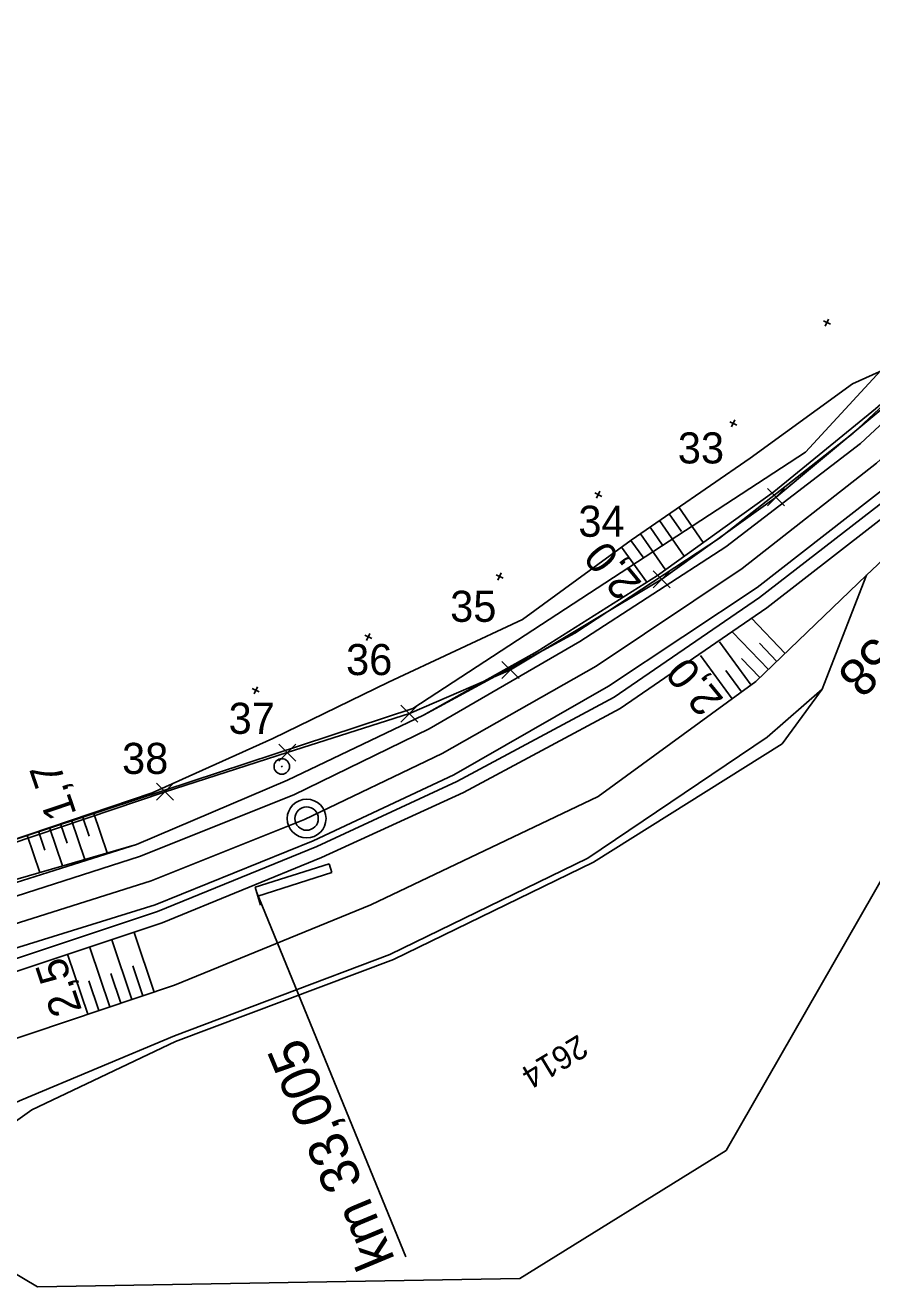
# Model space of a CAD drawing. Extents: x -804166 to -803706, y -1151030 to -1150147.
# Drawn here: x -803964.8 to -803910.3, y -1150743 to -1150661.8 of the extents above; entities that cross this region are included whole.
import ezdxf

# ---------------------------------------------------------------- set-up
doc = ezdxf.new("R2010")
doc.units = 0
for name, color, linetype in [('0381KM032-037P - Vrstva 1', 7, 'Continuous'), ('0381KM032-037P - Vrstva 13', 7, 'Continuous'), ('0381KM032-037P - Vrstva 4', 7, 'Continuous'), ('0381KM032-037P - Vrstva 48', 7, 'Continuous'), ('0381KM032-037P - Vrstva 49', 7, 'Continuous'), ('0381KM032-037P - Vrstva 57', 7, 'Continuous'), ('0381KM032-037P - Vrstva 7', 7, 'Continuous'), ('0381KM032-037P - Vrstva 9', 7, 'Continuous'), ('Default', 7, 'Continuous'), ('hran DP - hran DP', 7, 'Continuous'), ('PSR_C2_2_Lomove_body_Vimperk - Vrstva 60', 7, 'Continuous'), ('PSR_C2_2_trasa_Vimperk - Kabelová trasa', 7, 'Continuous'), ('vyt_sit - stávající', 7, 'Continuous')]:
    doc.layers.add(name, color=color, linetype=linetype)

msp = doc.modelspace()

# ---------------------------------------------------------------- linework, layer by layer
at = {"layer": '0381KM032-037P - Vrstva 1'}
msp.add_lwpolyline([(-803901.906, -1150682.605), (-803910.014, -1150690), (-803918.643, -1150696.775), (-803928.041, -1150703.062), (-803937.946, -1150708.688), (-803946.795, -1150712.932), (-803956.655, -1150716.869), (-803966.853, -1150720.098), (-803973.694, -1150721.813), (-803983.505, -1150723.682), (-803993.918, -1150724.91), (-804004.459, -1150725.421), (-804014.948, -1150725.206), (-804025.475, -1150724.252), (-804035.41, -1150722.673), (-804044.081, -1150720.735), (-804054.774, -1150717.615), (-804061.472, -1150715.138)], dxfattribs=at)
at = {"layer": '0381KM032-037P - Vrstva 13'}
for points in [[(-803902.54, -1150686.99), (-803908.533, -1150691.682), (-803917.537, -1150698.646), (-803926.885, -1150705.063), (-803937.003, -1150710.487), (-803946.017, -1150714.661), (-803956.263, -1150718.85), (-803966.288, -1150722.189), (-803972.538, -1150724.259)], [(-803972.286, -1150725.012), (-803966.125, -1150722.974), (-803955.955, -1150719.581), (-803945.709, -1150715.376), (-803936.565, -1150711.19), (-803926.506, -1150705.78), (-803917.073, -1150699.315), (-803908.044, -1150692.29), (-803902.092, -1150687.65)]]:
    msp.add_lwpolyline(points, dxfattribs=at)
at = {"layer": '0381KM032-037P - Vrstva 4'}
for points in [[(-803904.886, -1150683.001), (-803906.516, -1150683.391), (-803911.518, -1150688.069), (-803920.109, -1150694.835), (-803929.412, -1150700.935), (-803939.155, -1150706.209), (-803947.889, -1150710.398), (-803957.601, -1150714.533), (-803967.413, -1150717.637)], [(-803904.886, -1150683.001), (-803911.05, -1150688.735), (-803919.705, -1150695.384), (-803929.087, -1150701.477), (-803938.787, -1150707.105), (-803947.481, -1150711.337), (-803957.418, -1150715.321), (-803967.176, -1150718.433)], [(-803902.503, -1150685.469), (-803908.943, -1150691.185), (-803917.694, -1150697.991), (-803927.241, -1150704.348), (-803937.195, -1150710.055), (-803946.246, -1150714.302), (-803956.405, -1150718.419), (-803966.448, -1150721.526)], [(-803902.503, -1150685.469), (-803902.54, -1150686.99), (-803908.533, -1150691.682), (-803917.537, -1150698.646), (-803926.885, -1150705.063), (-803937.003, -1150710.487), (-803946.017, -1150714.661), (-803956.263, -1150718.85), (-803966.288, -1150722.189)]]:
    msp.add_lwpolyline(points, dxfattribs=at)
at = {"layer": '0381KM032-037P - Vrstva 48'}
for p, q in [((-803923.341, -1150693.265), (-803922.553, -1150694.407)), ((-803922.724, -1150692.839), (-803921.156, -1150695.111)), ((-803924.575, -1150694.118), (-803923.779, -1150695.271)), ((-803923.958, -1150693.691), (-803922.374, -1150695.987)), ((-803925.809, -1150694.97), (-803924.975, -1150696.112)), ((-803925.193, -1150694.544), (-803923.592, -1150696.863)), ((-803926.415, -1150695.413), (-803924.777, -1150697.655)), ((-803915.883, -1150702.24), (-803918.059, -1150699.974)), ((-803916.965, -1150703.279), (-803919.272, -1150700.876)), ((-803918.079, -1150704.279), (-803920.11, -1150701.499)), ((-803916.424, -1150702.759), (-803917.545, -1150701.592)), ((-803919.291, -1150705.163), (-803921.33, -1150702.372)), ((-803918.685, -1150704.721), (-803919.698, -1150703.334)), ((-803917.506, -1150703.798), (-803918.692, -1150702.563)), ((-803961.787, -1150712.97), (-803960.933, -1150715.502)), ((-803961.077, -1150712.73), (-803960.645, -1150714.011)), ((-803960.366, -1150712.49), (-803959.492, -1150715.083)), ((-803963.919, -1150713.689), (-803963.508, -1150714.91)), ((-803963.209, -1150713.449), (-803962.375, -1150715.921)), ((-803962.498, -1150713.21), (-803962.076, -1150714.461)), ((-803964.63, -1150713.929), (-803963.816, -1150716.341)), ((-803956.479, -1150724.031), (-803957.763, -1150720.201)), ((-803959.324, -1150724.985), (-803960.603, -1150721.167)), ((-803957.902, -1150724.508), (-803959.183, -1150720.684)), ((-803960.746, -1150725.461), (-803962.023, -1150721.65)), ((-803958.613, -1150724.746), (-803959.253, -1150722.836)), ((-803957.19, -1150724.27), (-803957.832, -1150722.356)), ((-803960.035, -1150725.223), (-803960.674, -1150723.316))]:
    msp.add_line(p, q, dxfattribs=at)
at = {"layer": '0381KM032-037P - Vrstva 49'}
for p, q in [((-803913.423, -1150680.841), (-803912.971, -1150681.057)), ((-803913.089, -1150680.723), (-803913.305, -1150681.175)), ((-803919.449, -1150687.332), (-803918.997, -1150687.548)), ((-803919.115, -1150687.214), (-803919.331, -1150687.666)), ((-803928.133, -1150691.918), (-803927.681, -1150692.134)), ((-803927.799, -1150691.8), (-803928.015, -1150692.252)), ((-803934.479, -1150697.185), (-803934.027, -1150697.401)), ((-803934.145, -1150697.067), (-803934.361, -1150697.519)), ((-803942.927, -1150701.07), (-803942.475, -1150701.286)), ((-803942.593, -1150700.952), (-803942.809, -1150701.404)), ((-803950.166, -1150704.501), (-803949.714, -1150704.717)), ((-803949.832, -1150704.383), (-803950.048, -1150704.835))]:
    msp.add_line(p, q, dxfattribs=at)
for points in [[(-803984.817, -1150721.442), (-803974.636, -1150719.233), (-803973.09, -1150718.927), (-803972.805, -1150718.807), (-803972.246, -1150718.741), (-803965.21, -1150716.746), (-803957.601, -1150714.533), (-803947.889, -1150710.398), (-803939.155, -1150706.209), (-803931.831, -1150702.119), (-803924.086, -1150697.218), (-803916.608, -1150691.841), (-803910.081, -1150686.51), (-803906.516, -1150683.391), (-803903.605, -1150681.318)], [(-803972.246, -1150718.741), (-803965.841, -1150714.337), (-803956.596, -1150711.219), (-803948.841, -1150707.727), (-803941.393, -1150704.085), (-803932.776, -1150700.061), (-803925.787, -1150694.954), (-803918.146, -1150689.679), (-803911.549, -1150684.903), (-803903.605, -1150681.318)], [(-803973.24, -1150730.36), (-803966.718, -1150727.463), (-803955.163, -1150723.59), (-803942.536, -1150718.416), (-803927.909, -1150711.458), (-803917.773, -1150704.055), (-803910.649, -1150697.212), (-803903.52, -1150690.487), (-803900.099, -1150686.57)], [(-803902.092, -1150687.65), (-803908.044, -1150692.29), (-803917.073, -1150699.315), (-803926.506, -1150705.78), (-803936.565, -1150711.19), (-803945.709, -1150715.376), (-803955.955, -1150719.581), (-803966.125, -1150722.974), (-803972.286, -1150725.012), (-803974.7, -1150725.768), (-803983.368, -1150727.37), (-803993.836, -1150727.905), (-804004.989, -1150728.615), (-804004.868, -1150729.928), (-804012.985, -1150730.258), (-804018.762, -1150729.808), (-804029.792, -1150728.642), (-804054.152, -1150723.147), (-804060.274, -1150720.943)], [(-803970.39, -1150735.93), (-803964.347, -1150731.606), (-803955.102, -1150727.225), (-803941.078, -1150721.948), (-803928.207, -1150715.68), (-803916.068, -1150708.06), (-803913.504, -1150704.534), (-803910.649, -1150697.212)], [(-803971.76, -1150733.922), (-803964.987, -1150730.973), (-803955.152, -1150726.847), (-803941.304, -1150721.616), (-803928.584, -1150715.413), (-803917.051, -1150707.621), (-803913.504, -1150704.534)]]:
    msp.add_lwpolyline(points, dxfattribs=at)
at = {"layer": '0381KM032-037P - Vrstva 7'}
msp.add_line((-803948.213, -1150709.499), (-803948.305, -1150709.537), dxfattribs=at)
for centre, radius in [((-803948.259, -1150709.518), 0.5), ((-803946.663, -1150712.869), 1.246), ((-803946.663, -1150712.869), 0.752)]:
    msp.add_circle(centre, radius, dxfattribs=at)
at = {"layer": '0381KM032-037P - Vrstva 9'}
for p, q in [((-803945.217, -1150715.777), (-803949.983, -1150717.29)), ((-803945.036, -1150716.348), (-803945.217, -1150715.777)), ((-803949.801, -1150717.862), (-803945.036, -1150716.348)), ((-803949.983, -1150717.29), (-803949.801, -1150717.862)), ((-803949.892, -1150717.576), (-803940.281, -1150741.083)), ((-803949.801, -1150717.862), (-803949.62, -1150718.434))]:
    msp.add_line(p, q, dxfattribs=at)
at = {"layer": 'hran DP - hran DP'}
for p, q in [((-803914.58, -1150689.29), (-803907.67, -1150681.78)), ((-803939.84, -1150705.78), (-803914.58, -1150689.29)), ((-803967.26, -1150714.81), (-803939.84, -1150705.78)), ((-803905.7, -1150709.82), (-803919.68, -1150734.23)), ((-803919.68, -1150734.23), (-803932.96, -1150742.47)), ((-803963.98, -1150743), (-803968.3, -1150740.45)), ((-803932.96, -1150742.47), (-803963.98, -1150743))]:
    msp.add_line(p, q, dxfattribs=at)
at = {"layer": 'PSR_C2_2_Lomove_body_Vimperk - Vrstva 60'}
for p, q in [((-803917.018, -1150692.734), (-803915.918, -1150691.634)), ((-803915.918, -1150692.734), (-803917.018, -1150691.634)), ((-803924.372, -1150698.021), (-803923.272, -1150696.921)), ((-803923.272, -1150698.021), (-803924.372, -1150696.921)), ((-803934.101, -1150703.856), (-803933.001, -1150702.756)), ((-803933.001, -1150703.856), (-803934.101, -1150702.756)), ((-803940.605, -1150706.662), (-803939.505, -1150705.562)), ((-803939.505, -1150706.662), (-803940.605, -1150705.562)), ((-803948.461, -1150709.177), (-803947.361, -1150708.077)), ((-803947.361, -1150709.177), (-803948.461, -1150708.077)), ((-803956.316, -1150711.692), (-803955.216, -1150710.592)), ((-803955.216, -1150711.692), (-803956.316, -1150710.592))]:
    msp.add_line(p, q, dxfattribs=at)
at = {"layer": 'PSR_C2_2_trasa_Vimperk - Kabelová trasa'}
msp.add_line((-803965.797, -1150714.54), (-803955.766, -1150711.142), dxfattribs=at)
for points in [[(-803940.055, -1150706.112), (-803933.551, -1150703.306), (-803923.822, -1150697.471), (-803916.468, -1150692.184), (-803905.701, -1150683.196), (-803894.808, -1150671.7), (-803893.852, -1150661.817)], [(-803955.766, -1150711.142), (-803947.911, -1150708.627), (-803940.055, -1150706.112)]]:
    msp.add_lwpolyline(points, dxfattribs=at)

# ---------------------------------------------------------------- texts
at = {"layer": '0381KM032-037P - Vrstva 48'}
for s, rotation, p in [('2,0', 129.61944, (-803925.039, -1150697.72)), ('2,0', 129.42518, (-803919.779, -1150705.196)), ('1,7', 108.63737, (-803961.445, -1150712.571)), ('2,5', 108.45016, (-803961.097, -1150725.192))]:
    msp.add_text(s, height=2, rotation=rotation, dxfattribs=at).set_placement(p)
at = {"layer": '0381KM032-037P - Vrstva 57'}
msp.add_text('2614', height=1.5, rotation=211.19956, dxfattribs=at).set_placement((-803929.177, -1150726.725))
at = {"layer": '0381KM032-037P - Vrstva 9'}
msp.add_text('km 33,005', height=2.5, rotation=112.61933, dxfattribs=at).set_placement((-803940.96, -1150741.243))
at = {"layer": 'Default'}
for s, p in [('33', (-803922.788, -1150690.017)), ('34', (-803929.185, -1150694.736)), ('35', (-803937.432, -1150700.21)), ('36', (-803944.128, -1150703.637)), ('37', (-803951.682, -1150707.418)), ('38', (-803958.536, -1150709.998))]:
    msp.add_text(s, height=2, dxfattribs=at).set_placement(p)
at = {"layer": 'vyt_sit - stávající'}
msp.add_text('ŽP 758', height=2.4, rotation=225, dxfattribs=at).set_placement((-803905.333, -1150696.219))

doc.saveas('drawing.dxf')
